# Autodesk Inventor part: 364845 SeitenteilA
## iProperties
Company: Mayer & Müller AG Schaltgeräte
Created: 2011-07
Part Number: 364845 SeitenteilA
Material: 1.0120
Document SubType Name: Modeling
Designer: I.Baliuc
Manufacturer: Standard
Standards Organization: Custom
Description: Seitenteil, Trenner
Cost Center: 5,196 kg
Authority: 661896 mm^3
Density: 7.85 g/cm^3
HalbzeugNorm: DIN 174
Zweck: HSLT / HSE - Standardseite
Abmessung: Fl. 120x12-170
SaveDate: 2006-10-28
SaveTime: 20:23
TotalMass: 5,196 kg
TotalVolume: 661896 mm^3
Author: GDK-8530w-2
Revision Number: 364845
Keywords: 380125
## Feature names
1. Extrusion2
2. Bohrung_Ø13 [Hole]
3. Bohrung2 [Hole]
4. Bohrung3 [Hole]
5. Bohrung_M8_01 [Hole]
6. Bohrung_M8_02 [Hole]
7. Bohrung_M6 [Hole]
8. Bohrung_M5 [Hole]
9. Neue Bohrung (zusätzlich) [Rectangular Pattern]
